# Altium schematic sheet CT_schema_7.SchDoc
size 405 x 220 mm
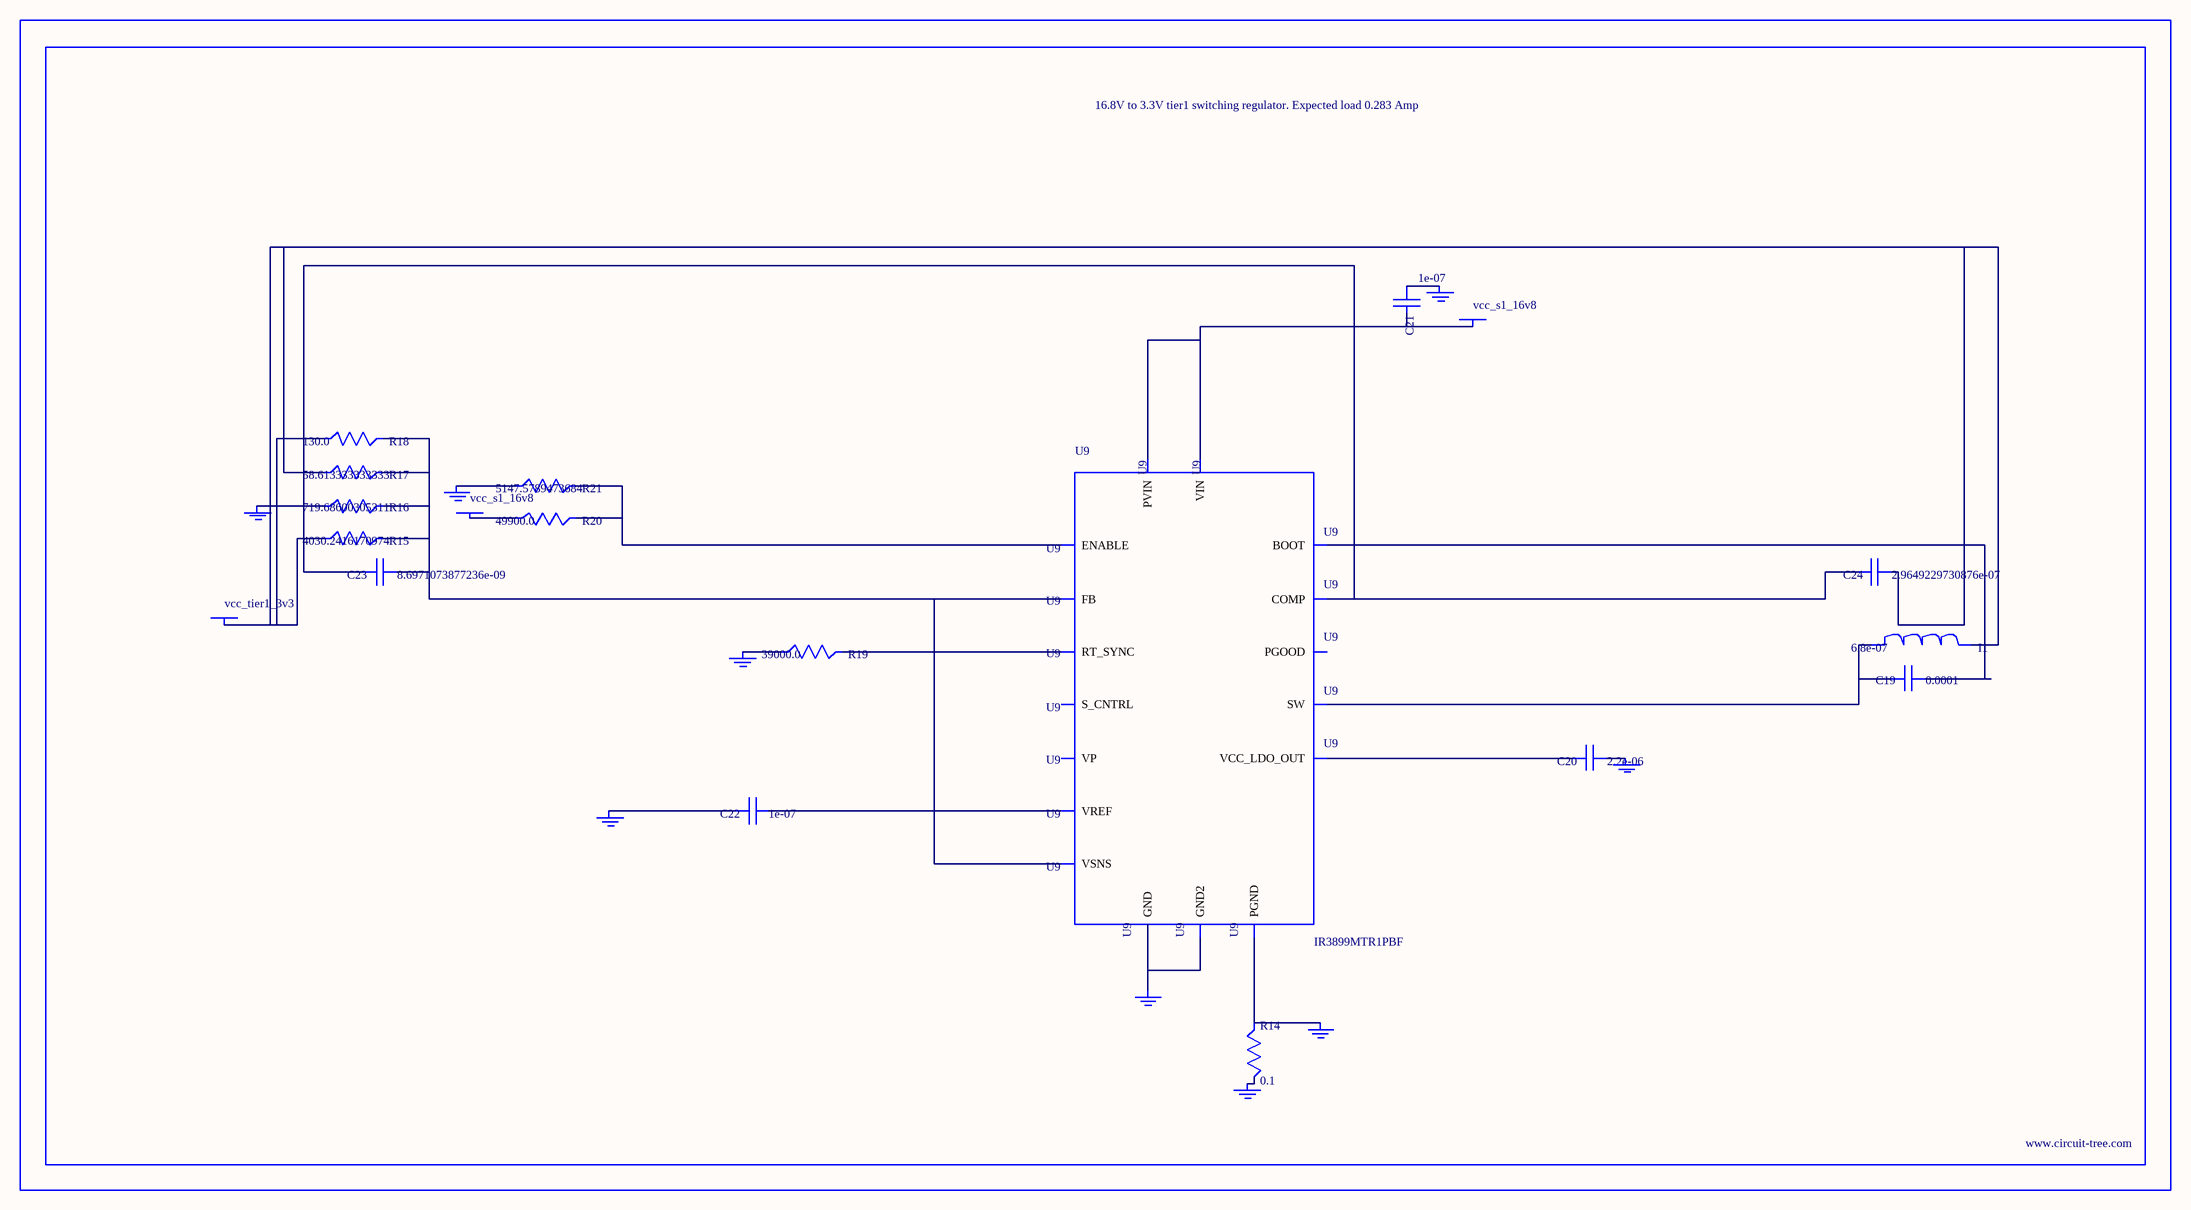
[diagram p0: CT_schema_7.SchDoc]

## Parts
BORDER6  (no value)
C19  0.0001  [C1210]
C20  2.2e-06  [C0603]
C21  1e-07  [C0402]
C22  1e-07  [C0402]
C23  8.6971073877236e-09  [R0603]
C24  2.9649229730876e-07  [R0603]
GND_INSTANCE_6_0  (no value)
GND_INSTANCE_6_1  (no value)
GND_INSTANCE_6_2  (no value)
GND_INSTANCE_6_3  (no value)
GND_INSTANCE_6_4  (no value)
GND_INSTANCE_6_5  (no value)
GND_INSTANCE_6_6  (no value)
GND_INSTANCE_6_7  (no value)
GND_INSTANCE_6_8  (no value)
I1  6.8e-07  [IND25X25CZ]
POWER_INSTANCE_6_0  vcc_s1_16v8
POWER_INSTANCE_6_1  vcc_s1_16v8
POWER_INSTANCE_6_2  vcc_tier1_3v3
R14  0.1  [R0603]
R15  4030.2416170974  [R0603]
R16  719.68600305311  [R0603]
R17  58.613333333333  [R0603]
R18  130.0  [R0603]
R19  39000.0  [R0603]
R20  49900.0  [R0603]
R21  5147.5789473684  [R0603]
U9  IR3899MTR1PBF  [IR3899MTR1PBF]

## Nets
NetC19_1: C19.1 U9.14(BOOT)
NetC19_2: C19.2 I1.1 U9.12(SW)
NetC20_1: C20.1 GND_INSTANCE_6_4.0(GND)
NetC20_2: C20.2 U9.10(VCC_LDO_OUT)
NetC21_1: C21.1 GND_INSTANCE_6_3.0(GND)
NetC21_2: C21.2 POWER_INSTANCE_6_0.0(PWR) U9.9(VIN) U9.13(PVIN)
NetC22_1: C22.1 U9.2(VREF)
NetC22_2: C22.2 GND_INSTANCE_6_1.0(GND)
NetC23_1: C23.1 R15.2 R16.2 R17.2 R18.2 U9.1(FB) U9.8(VSNS)
NetC23_2: C23.2 C24.2 U9.3(COMP)
NetC24_1: C24.1 I1.2 POWER_INSTANCE_6_2.0(PWR) R15.1 R17.1 R18.1
NetGND_INSTANCE_6_0_0: GND_INSTANCE_6_0.0(GND) R16.1
NetGND_INSTANCE_6_2_0: GND_INSTANCE_6_2.0(GND) R19.1
NetGND_INSTANCE_6_5_0: GND_INSTANCE_6_5.0(GND) R14.2
NetGND_INSTANCE_6_6_0: GND_INSTANCE_6_6.0(GND) R14.1 U9.11(PGND)
NetGND_INSTANCE_6_7_0: GND_INSTANCE_6_7.0(GND) R21.1
NetGND_INSTANCE_6_8_0: GND_INSTANCE_6_8.0(GND) U9.4(GND) U9.17(GND2)
NetPOWER_INSTANCE_6_1_0: POWER_INSTANCE_6_1.0(PWR) R20.1
NetR19_2: R19.2 U9.5(RT_SYNC)
NetR20_2: R20.2 R21.2 U9.15(ENABLE)

Not connected (* = marked no-connect by the designer): U9 6(S_CNTRL) 7(PGOOD) 16(VP)

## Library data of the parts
BORDER6 = BORDER_PAGE6
C19 = GRM32ER61A107ME20L
C20 = C0603C225K8RACTU
C21 C22 = C0402C104K3RACTU
C23 = C23
C24 = C24
GND_INSTANCE_6_0-GND_INSTANCE_6_8 = GND
I1 = IHLP2525CZERR68M01
POWER_INSTANCE_6_0-POWER_INSTANCE_6_2 = PWR
R14 = ERJ-3RSFR10V
R15 = R15
R16 = R16
R17 = R17
R18 = RC0603JR-07130RL
R19 = RC0603JR-0739KL
R20 = RC0603FR-0749K9
R21 = R21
